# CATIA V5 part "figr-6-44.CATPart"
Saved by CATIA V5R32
Part number: Part1
Bounding box of the stored display mesh (mm): x -26.811 to 26.811, y -47.298 to 47.298, z 0 to 31.431
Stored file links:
  D:\PROJECTS\Project 2022\CATIA V5 6R 2022\Resources\Part Files\c06_catia_v5_6r2022_prt\figr-6-44.CATPart
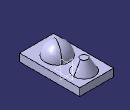
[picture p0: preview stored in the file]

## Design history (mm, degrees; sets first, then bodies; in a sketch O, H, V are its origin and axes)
Body1 (main body)
  Sketch1 on xy-plane, origin (0, 0, 0), H (1, 0, 0), V (0, 1, 0)
    line L1 (-26.8114, 47.2981) -> (26.8114, 47.2981)
    line L2 (26.8114, 47.2981) -> (26.8114, -47.2981)
    line L3 (26.8114, -47.2981) -> (-26.8114, -47.2981)
    line L4 (-26.8114, -47.2981) -> (-26.8114, 47.2981)
    axis line L5 (26.8114, -47.2981) -> (-26.8114, 47.2981)
    horizontal: L1 H, L3 H
    vertical: L2 V, L4 V
    coincidence: L5 O
    midpoint: L5 O
  Pad1: profile Sketch1, direction (0, 0, 1), length 12
  Sketch2 on yz-plane, origin (0, 0, 0), H (0, 1, 0), V (0, 0, 1)
    axis line L1 (-14.846, 35.4307) -> (-14.846, -5.9324)
    arc A1 centre (-14.846, 12.2093) radius 19.2216 from (-14.846, 31.431) to (-33.1926, 6.476) ccw
    point P3 (-14.846, 12.2093)
    point P4 (-14.846, 31.431)
    line L2 (-14.846, 31.431) -> (-14.846, 8.3996)
    line L3 (-14.846, 8.3996) -> (-33.1926, 6.476)
    vertical: L1 V, L2 V
    coincidence: P3 L1, P4 L1, A1 O
  Shaft1: profile Sketch2, axis Sketch2.L1, angle 360
  Sketch3 on face of Pad1, origin (0, 0, 12), H (1, 0, 0), V (0, 1, 0)
    circle A1 centre (0, 27.4246) radius 16.1543
    point P1 (0, 27.4246)
    coincidence: P1 V
  Pad2: profile Sketch3, direction (0, 0, 1), length 18
  Draft1: Angle 30, Neutral face of Pad1, PullDir face of Pad1, SupportToDraft face of Pad2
